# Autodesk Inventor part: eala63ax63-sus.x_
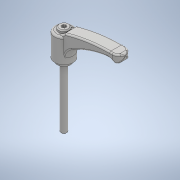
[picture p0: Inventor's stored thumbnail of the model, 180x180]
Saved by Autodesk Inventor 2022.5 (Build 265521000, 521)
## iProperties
Created: 2018-05
Part Number: eala63ax63-sus.x_
Material: 一般
Document SubType Name: Modeling
Designer: imaocorp
Density: 1 g/cm^3
Appearance: 既定
Sending System: SOLIDWORKS 2016-2016286
MC: AMD64
MC_MODEL: AMD64 Family 21 Model 2 Stepping 0, AuthenticAMD
OS: Windows_NT
FRU: Parasolid Version 28.0, build 224,  7-29-2016
FORMAT: text
GUISE: transmit
KEY: eala63ax63-sus
FILE: eala63ax63-sus.x_t
DATE: Fri May 18 11:30:06 2018
Author: imaocorp
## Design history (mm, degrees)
feature "Base1"
node "ソリッド1"
